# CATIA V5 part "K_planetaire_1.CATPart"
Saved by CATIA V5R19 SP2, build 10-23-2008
Part number: planetaire 1
Source: Unknown
Publications: "Face", "diam prim", "longueur portée", "R portée"
Material "Aucun"
Bounding box of the stored display mesh (mm): x -121.726 to 121.726, y -121.726 to 121.726, z -23 to 22.385
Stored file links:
  G:\Khaled_CFAO_2011\ST2M\ST2M_GR1\mponsin\Khaled\CAD_ThinkMOTION\K_planetaire_1.CATPart
  C:\Program Files\Dassault Systemes\B20\win_b64\startup\materials\French\Catalog.CATMaterial
  C:\Users\Socar\Documents\thinkmotion\Final\Diff2.CATProduct
  G:\Khaled_CFAO_2011\ST2M\ST2M_GR1\mponsin\Khaled\CAD_ThinkMOTION\K_mponsin.CATProduct
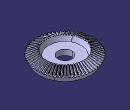
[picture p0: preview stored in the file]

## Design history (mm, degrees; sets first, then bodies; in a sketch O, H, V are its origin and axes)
Parameters
  Z1 = 60 {= External.Zp}
  delta = 63.4349 deg {= atan(External.Zp /External.Zs )}
  a = 20 deg
  m = 4 mm {= External.Module}
  ld = 44.7214 mm {= m *Z1 /(3*2*sin(delta ))}
  dZ = 0 mm
  p = 12.5664 mm {= m * PI}
  rp = 120 mm {= m * Z1 / 2}
  rc = 268.3282 mm {= rp / cos( delta )}
  rb = 252.146 mm {= rc * cos( a )}
  lc = 300 mm {= rc / sin( delta )}
  ha = 4 mm {= m}
  hf = 5 mm {= 1.25 * m}
  rr = 1.2196 mm {= Set2.Offset * 0.7763}
  tc = -0.7576 deg
  ratio = 0.666667 {= 1 - ld / lc / cos( delta )}
  `diam prim` = 240 mm {= m *Z1}
  `R portée` = 40 mm {= `External.R cardan` + 10mm}
  `longueur portée` = 3 mm
External parameters (linked from other documents)
  External.Zp = 60
  External.Zs = 30
  External.Module = 4 mm
  `External.R cardan` = 30 mm
Intersect1 "coin de fond": ToIntersect1 Project1, ToIntersect2 Circle4
Point1: type OnCurve, Support Line7, Length 5 {= hf}
Set1 "cones primitifs"
  Line1 "Axe Z": stored without definition
  Point2 "sommet arriere": (0, 0, -240 {= dZ - rp * tan( delta )})
  Point3 "sommet avant": type OnCurve, Support Line1, RefPoint Point2, Length 300 {= lc}
  Line2: type PtPt, FirstPoint Point2, SecondPoint Point3
  Line3: type Angle, RefPoint Point3, Curve Line2, Support zx-plane, Start 0, End 134.1641 {= lc * cos( delta )}, Angle -63.4349 {= -delta}
  Line4: type PtPt, FirstPoint Point2, SecondPoint vertex of Line3, Start 0
  Plane1 "plan_primitif": type OffsetPt, RefPlane xy-plane, RefPoint vertex of Line3
  Intersect2: ToIntersect1 Plane1, ToIntersect2 Line2
  Circle1 "arc primitif": type CtrPt, Start 0, End 30, Center Intersect2, Support Plane1, RefPoint vertex of Line3
  Circle2 "cercle primitif": type CtrRad, Start 0, End 90, Center Intersect2, Support Plane1, Radius 120 {= rp}, FirstDirection (1, 0, 0)
Set2 "profil dent"
  Point4 "point 0": type OnPlane, Support Plane2, RefPoint Point2, H 252.146, V 0, Direction (1, 0, 0)
  Point5 "point 1": type OnPlane, Support Plane2, RefPoint Point2, H 264.2836, V 2.5804, Direction (1, 0, 0)
  Point6 "point 2": type OnPlane, Support Plane2, RefPoint Point2, H 297.112, V 20.0368, Direction (1, 0, 0)
  Point7 "point 3": type OnPlane, Support Plane2, RefPoint Point2, H 340.4641, V 64.3079, Direction (1, 0, 0)
  Curve1: Elements (Point4; Point5; Point6; Point7)
  Extrapol1: ToExtrapol Point4, Support Curve1, Length 8 {= 2 * m}
  Plane2: type Normal, Curve Line3, RefPoint Point2
  Symmetry1: Reference vertex of Line3, ToTransfor Point2
  Line5: type PtPt, FirstPoint Point2, SecondPoint Symmetry1
  Point8: type OnCurve, Support Line5, Ratio 0.25
  Line6: type PtPt, FirstPoint Point8, SecondPoint vertex of Line5
  Revol1: Element1 Line6, Line Line1, Angle1 0
  Project1: ToProject Extrapol1, Support Revol1, Direction Line3
  Intersect3: ToIntersect1 Circle1, ToIntersect2 Project1
  Plane3 "plan contact": type 1Line1Pt, RefPoint Intersect3, Line Line1
  Circle3 "cercle primitif": type CtrPt, Start 1.5 {= 90deg / Z1}, End -1.5 {= -90deg / Z1}, Center Intersect2, Support Plane1, RefPoint Intersect3
  Plane4 "plan median": type 1Line1Pt, RefPoint vertex of Circle3, Line Line1
  Line7 "droite debut": type PtPt, FirstPoint vertex of Circle3, SecondPoint Point2
  Plane5 "plan_fond": type OffsetPt, RefPlane xy-plane, RefPoint Point1
  Intersect4: ToIntersect1 Plane5, ToIntersect2 Line2
  Circle4 "cercle de fond": type CtrPt, Start 0, End 30, Center Intersect4, Support Plane5, RefPoint Point1
  Point9: type OnCurve, Support Line7, Length -4 {= -ha}
  Plane6 "plan_tete": type OffsetPt, RefPlane xy-plane, RefPoint Point9
  Intersect5: ToIntersect1 Plane6, ToIntersect2 Line2
  Circle5 "cercle de tete": type CtrPt, Start 0, End 30, Center Intersect5, Support Plane6, RefPoint Point9
  Split1 "segment flanc": ToCut Project1, Cutting Plane5
  Split2 "segment fond": ToCut Circle4, Cutting Project1
  Corner1: Element1 Split1, Element2 Split2, Support Revol1, Radius 1.194 {= Set2.Offset * 0.76}
  Symmetry2: Reference Plane4, ToTransfor Corner1
  Trim1: Element1 Corner1, Element2 Circle5
  Trim2: Element1 Trim1, Element2 Symmetry2
Set3 "surface dent"
  Point10 "fin denture": type OnCurve, Support Line3, Length 44.7214 {= ld}
  Scaling1: Reference Point3, Ratio 0.666667 {= ratio}, ToTransfor Trim2
  Line8: type PtPt, FirstPoint vertex of Scaling1, SecondPoint Point1
  Line9: type PtPt, FirstPoint vertex of Scaling1, SecondPoint vertex of Trim2
  Loft1: Sections (Trim2; Scaling1), Guides (Line8; Line9)
  CircPattern1: of Loft1, instances 60 {= Z1}, angular step 6 {= 360.0*1 deg/CircPattern1.AngularNumber}, axis from Line2
Set4 "flanc dent"
  CircPattern2: of Trim2, instances 60 {= Z1}, angular step 6 {= 360.0*1 deg/CircPattern2.AngularNumber}, axis from Line2
  Join1: Elements (CircPattern2; Trim2)
  Split3: ToCut Revol1, Cutting Join1
  Scaling2: Reference Point3, Ratio 0.666667 {= ratio}, ToTransfor Split3
  Fill1: Boundary edge of Scaling2
  Join2: Elements (Split3; CircPattern1; Scaling2; Fill1; Loft1)
Body1 (main body)
  Sketch1 on zx-plane, origin (0, 0, 0), H (-1, 0, 0), V (0, 0, 1)
    point P1 (-60, -120)
    line L1 (0, 0) -> (0, -123.9213)
    line L2 (0, -123.9213) -> (-60, -123.9213)
    line L3 (-60, -123.9213) -> (-60, -120)
    reference projected point E1 (-60, -120) from Point8
    line L4 (-60, -120) -> (-120, 0)
    point P5 (-120, 0)
    line L5 (0, 0) -> (-120, 0)
    reference projected point E2 (-120, 0) from vertex of Line4
    horizontal: L2 H, L5 H
    vertical: L1 V, L3 V
    coincidence: P1 E1, L1 V, P5 E2
  Shaft1: profile Sketch1, axis Line1, angle 360
  CloseSurface1: CloseElement Join2
  Sketch2 on xy-plane, origin (0, 0, 0), H (1, 0, 0), V (0, 1, 0)
    circle A1 centre (0, 0) radius 30
    radius A1 = 30 {= `External.R cardan`}
  Pocket1: profile Sketch2, direction (0, 0, 1), through (limit type 6), opposite side through (limit type 6)
  Body2
    Sketch3 on zx-plane, origin (0, 0, 0), H (-1, 0, 0), V (0, 0, 1)
      line L1 (0, -240) -> (520, -20)
      point P1 (0, -240)
      point P2 (520, -20)
      line L2 (520, -20) -> (40, -20)
      point P3 (520, -20)
      line L3 (40, -20) -> (40, -23)
      line L4 (40, -23) -> (0, -23)
      point P6 (0, -23)
      line L5 (0, -23) -> (0, -240)
      reference projected point E1 (0, -240) from Point2
      length L3 = 3 {= `longueur portée`}
      length L4 = 40 {= `R portée`}
      distance L2 H = 20
      length L2 = 480 {= 2*`diam prim`}
      coincidence: P1 V, P3 L1, P6 V, P2 P3, P1 E1
      horizontal: L2 H, L4 H
      vertical: L3 V, L5 V
    Shaft2: profile Sketch3, axis Sketch3.L5, angle 360
  Remove1: tool Body2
